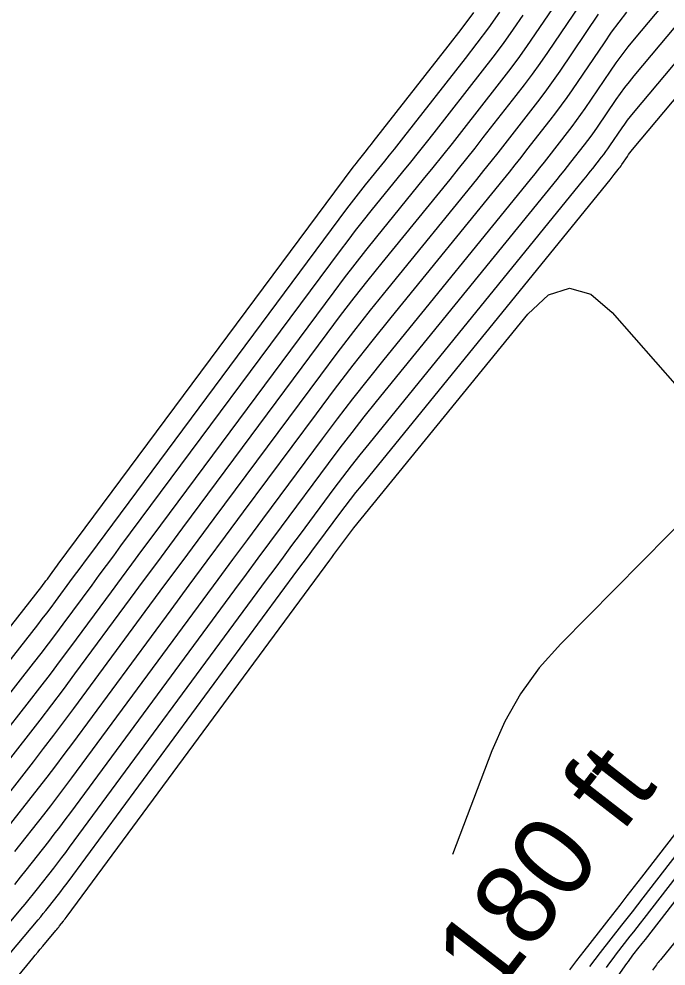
# Model space of a CAD drawing. Extents: x 7585033 to 7595090, y 547091 to 553471.
# Drawn here: x 7587152.7 to 7587203.3, y 548340.9 to 548414.8 of the extents above; entities that cross this region are included whole.
import ezdxf

# ---------------------------------------------------------------- set-up
doc = ezdxf.new("R2010")
doc.units = 0
for name, color, linetype in [('E_TERR_DSPLAY_GeneralTx', 7, 'Continuous'), ('E_TERR_DSPLAY_MajContour', 7, 'Continuous'), ('E_TERR_DSPLAY_MinContour', 7, 'Continuous')]:
    doc.layers.add(name, color=color, linetype=linetype)

msp = doc.modelspace()

# ---------------------------------------------------------------- linework, layer by layer
at = {"layer": 'E_TERR_DSPLAY_MajContour'}
for points in [[(7587216.392, 548431.831), (7587200.8, 548413.242), (7587200.305, 548412.638), (7587199.827, 548412.021), (7587199.365, 548411.392), (7587198.918, 548410.751), (7587196.942, 548407.837), (7587196.61, 548407.357), (7587196.27, 548406.882), (7587195.921, 548406.413), (7587195.565, 548405.95), (7587194.124, 548404.111), (7587193.762, 548403.652), (7587193.399, 548403.194), (7587193.033, 548402.738), (7587192.666, 548402.284), (7587181.228, 548388.221), (7587180.001, 548386.696), (7587178.791, 548385.157), (7587177.598, 548383.606), (7587176.422, 548382.041), (7587171.751, 548375.755), (7587170.584, 548374.183), (7587169.418, 548372.61), (7587168.254, 548371.036), (7587167.091, 548369.461), (7587156.836, 548355.558), (7587156.294, 548354.828), (7587155.746, 548354.102), (7587155.192, 548353.381), (7587154.633, 548352.663), (7587152.387, 548349.802)], [(7587197.116, 548419.631), (7587193.072, 548413.667), (7587192.392, 548412.683), (7587191.696, 548411.712), (7587190.983, 548410.753), (7587190.254, 548409.805), (7587187.304, 548406.041), (7587186.564, 548405.101), (7587185.821, 548404.165), (7587185.072, 548403.232), (7587184.32, 548402.303), (7587180.665, 548397.809), (7587179.811, 548396.747), (7587178.968, 548395.675), (7587178.136, 548394.594), (7587177.317, 548393.503), (7587163.108, 548374.38), (7587162.311, 548373.308), (7587161.516, 548372.235), (7587160.722, 548371.161), (7587159.928, 548370.086), (7587156.756, 548365.786), (7587155.959, 548364.714), (7587155.154, 548363.648), (7587154.342, 548362.588), (7587153.521, 548361.534), (7587148.87, 548355.611)], [(7587130.311, 548312.87), (7587153.801, 548341.463), (7587153.995, 548341.698), (7587154.19, 548341.933), (7587154.385, 548342.168), (7587154.581, 548342.402), (7587155.605, 548343.624), (7587155.68, 548343.716), (7587155.755, 548343.807), (7587155.83, 548343.9), (7587155.903, 548343.993), (7587156.196, 548344.366), (7587156.269, 548344.459), (7587156.341, 548344.553), (7587156.413, 548344.648), (7587156.483, 548344.743), (7587177.005, 548372.565), (7587177.161, 548372.777), (7587177.317, 548372.988), (7587177.474, 548373.199), (7587177.63, 548373.41), (7587178.257, 548374.253), (7587178.414, 548374.462), (7587178.574, 548374.671), (7587178.737, 548374.877), (7587178.901, 548375.081), (7587192.474, 548391.769), (7587194.099, 548393.268), (7587195.743, 548393.788), (7587197.406, 548393.33), (7587199.086, 548391.894), (7587205.846, 548384.193)], [(7587205.62, 548376.702), (7587195.055, 548366.03), (7587193.376, 548364.151), (7587191.919, 548362.129), (7587190.685, 548359.964), (7587189.673, 548357.656), (7587186.609, 548349.565)], [(7587198.63, 548340.753), (7587198.888, 548341.106), (7587199.151, 548341.455), (7587199.418, 548341.801), (7587200.494, 548343.179), (7587200.763, 548343.524), (7587201.032, 548343.869), (7587201.3, 548344.214), (7587201.568, 548344.559), (7587222.895, 548372.105)]]:
    msp.add_lwpolyline(points, dxfattribs=at)
at = {"layer": 'E_TERR_DSPLAY_MinContour'}
for points in [[(7587151.496, 548341.202), (7587154.227, 548344.462), (7587154.429, 548344.706), (7587154.63, 548344.951), (7587154.828, 548345.197), (7587155.024, 548345.445), (7587155.805, 548346.44), (7587156, 548346.69), (7587156.192, 548346.94), (7587156.383, 548347.193), (7587156.571, 548347.447), (7587174.527, 548371.789), (7587174.935, 548372.342), (7587175.343, 548372.893), (7587175.751, 548373.445), (7587176.16, 548373.996), (7587177.798, 548376.2), (7587178.21, 548376.748), (7587178.628, 548377.292), (7587179.053, 548377.832), (7587179.483, 548378.366), (7587198.925, 548402.271), (7587199.004, 548402.368), (7587199.082, 548402.466), (7587199.161, 548402.565), (7587199.238, 548402.663), (7587199.548, 548403.059), (7587199.625, 548403.158), (7587199.7, 548403.259), (7587199.773, 548403.361), (7587199.844, 548403.465), (7587200.269, 548404.091), (7587200.365, 548404.229), (7587200.465, 548404.364), (7587200.568, 548404.497), (7587200.674, 548404.627), (7587224.859, 548433.46)], [(7587222.037, 548432.917), (7587200.716, 548407.499), (7587200.48, 548407.211), (7587200.252, 548406.917), (7587200.032, 548406.617), (7587199.819, 548406.311), (7587198.877, 548404.922), (7587198.719, 548404.693), (7587198.556, 548404.467), (7587198.39, 548404.243), (7587198.221, 548404.023), (7587197.533, 548403.146), (7587197.361, 548402.927), (7587197.188, 548402.709), (7587197.014, 548402.492), (7587196.838, 548402.275), (7587180.064, 548381.651), (7587179.369, 548380.786), (7587178.683, 548379.914), (7587178.006, 548379.034), (7587177.339, 548378.147), (7587174.691, 548374.582), (7587174.029, 548373.691), (7587173.368, 548372.799), (7587172.708, 548371.906), (7587172.048, 548371.013), (7587156.66, 548350.15), (7587156.353, 548349.738), (7587156.043, 548349.328), (7587155.731, 548348.92), (7587155.415, 548348.514), (7587154.145, 548346.897), (7587153.826, 548346.494), (7587153.504, 548346.094), (7587153.178, 548345.696), (7587152.85, 548345.301), (7587148.411, 548340.002)], [(7587219.214, 548432.374), (7587200.758, 548410.371), (7587200.393, 548409.924), (7587200.04, 548409.469), (7587199.698, 548409.004), (7587199.368, 548408.531), (7587197.909, 548406.38), (7587197.664, 548406.025), (7587197.413, 548405.674), (7587197.156, 548405.328), (7587196.893, 548404.986), (7587195.829, 548403.628), (7587195.562, 548403.289), (7587195.293, 548402.952), (7587195.023, 548402.615), (7587194.752, 548402.28), (7587180.646, 548384.936), (7587179.685, 548383.741), (7587178.737, 548382.536), (7587177.802, 548381.32), (7587176.88, 548380.094), (7587173.221, 548375.169), (7587172.306, 548373.937), (7587171.393, 548372.704), (7587170.481, 548371.471), (7587169.57, 548370.237), (7587156.748, 548352.854), (7587156.323, 548352.283), (7587155.894, 548351.715), (7587155.461, 548351.15), (7587155.024, 548350.589), (7587153.266, 548348.349), (7587152.824, 548347.791), (7587152.378, 548347.237)], [(7587149.749, 548354.159), (7587153.461, 548358.886), (7587154.385, 548360.072), (7587155.299, 548361.264), (7587156.204, 548362.463), (7587157.101, 548363.669), (7587161.446, 548369.56), (7587162.469, 548370.945), (7587163.492, 548372.328), (7587164.517, 548373.711), (7587165.542, 548375.093), (7587176.812, 548390.259), (7587177.862, 548391.656), (7587178.928, 548393.042), (7587180.008, 548394.416), (7587181.104, 548395.778), (7587186.406, 548402.298), (7587187.063, 548403.109), (7587187.715, 548403.922), (7587188.364, 548404.739), (7587189.009, 548405.558), (7587191.582, 548408.842), (7587192.218, 548409.668), (7587192.84, 548410.504), (7587193.447, 548411.352), (7587194.039, 548412.21), (7587197.566, 548417.411)], [(7587146.233, 548359.968), (7587154.508, 548370.508), (7587154.619, 548370.65), (7587154.729, 548370.794), (7587154.838, 548370.938), (7587154.945, 548371.082), (7587155.374, 548371.663), (7587155.481, 548371.809), (7587155.588, 548371.954), (7587155.696, 548372.099), (7587155.803, 548372.244), (7587178.833, 548403.237), (7587178.96, 548403.405), (7587179.088, 548403.572), (7587179.218, 548403.738), (7587179.35, 548403.902), (7587179.883, 548404.556), (7587180.015, 548404.72), (7587180.147, 548404.885), (7587180.278, 548405.05), (7587180.409, 548405.215), (7587186.271, 548412.697), (7587187.28, 548414.007), (7587188.266, 548415.334)], [(7587190.283, 548415.347), (7587189.409, 548414.127), (7587188.515, 548412.922), (7587187.599, 548411.733), (7587182.776, 548405.579), (7587182.408, 548405.111), (7587182.038, 548404.645), (7587181.665, 548404.181), (7587181.291, 548403.718), (7587179.789, 548401.871), (7587179.416, 548401.408), (7587179.048, 548400.94), (7587178.685, 548400.468), (7587178.328, 548399.992), (7587158.238, 548372.956), (7587157.901, 548372.502), (7587157.564, 548372.047), (7587157.228, 548371.593), (7587156.892, 548371.138), (7587155.549, 548369.317), (7587155.212, 548368.863), (7587154.871, 548368.412), (7587154.526, 548367.963), (7587154.179, 548367.517), (7587147.112, 548358.515)], [(7587192.104, 548415.124), (7587191.338, 548414.015), (7587190.553, 548412.919), (7587189.749, 548411.837), (7587188.927, 548410.769), (7587185.144, 548405.942), (7587184.538, 548405.172), (7587183.929, 548404.405), (7587183.316, 548403.641), (7587182.699, 548402.88), (7587180.227, 548399.84), (7587179.613, 548399.077), (7587179.008, 548398.307), (7587178.411, 548397.531), (7587177.822, 548396.748), (7587160.673, 548373.668), (7587160.106, 548372.905), (7587159.54, 548372.141), (7587158.975, 548371.377), (7587158.41, 548370.612), (7587156.153, 548367.551), (7587155.585, 548366.788), (7587155.013, 548366.03), (7587154.434, 548365.275), (7587153.85, 548364.525), (7587147.991, 548357.063)], [(7587150.628, 548352.706), (7587153.852, 548356.812), (7587154.654, 548357.841), (7587155.448, 548358.877), (7587156.234, 548359.918), (7587157.013, 548360.965), (7587162.965, 548369.034), (7587164.215, 548370.729), (7587165.468, 548372.422), (7587166.722, 548374.114), (7587167.977, 548375.805), (7587176.307, 548387.015), (7587177.588, 548388.719), (7587178.887, 548390.41), (7587180.205, 548392.086), (7587181.542, 548393.747), (7587188.493, 548402.294), (7587189.053, 548402.985), (7587189.61, 548403.68), (7587190.163, 548404.376), (7587190.714, 548405.076), (7587192.91, 548407.878), (7587193.452, 548408.583), (7587193.983, 548409.297), (7587194.501, 548410.02), (7587195.007, 548410.752), (7587198.017, 548415.191)], [(7587151.508, 548351.254), (7587154.243, 548354.738), (7587154.923, 548355.611), (7587155.597, 548356.489), (7587156.264, 548357.373), (7587156.924, 548358.261), (7587164.613, 548368.685), (7587166.027, 548370.601), (7587167.444, 548372.516), (7587168.862, 548374.429), (7587170.281, 548376.341), (7587175.963, 548383.988), (7587177.394, 548385.891), (7587178.845, 548387.779), (7587180.317, 548389.651), (7587181.809, 548391.506), (7587190.579, 548402.289), (7587191.043, 548402.862), (7587191.504, 548403.437), (7587191.963, 548404.014), (7587192.419, 548404.593), (7587194.237, 548406.914), (7587194.687, 548407.498), (7587195.126, 548408.089), (7587195.555, 548408.688), (7587195.974, 548409.295), (7587198.467, 548412.971), (7587199.031, 548413.78), (7587199.614, 548414.573), (7587200.218, 548415.351)], [(7587177.99, 548309.416), (7587200.23, 548341.062), (7587200.345, 548341.223), (7587200.462, 548341.382), (7587200.58, 548341.54), (7587200.701, 548341.697), (7587201.188, 548342.32), (7587201.31, 548342.476), (7587201.431, 548342.632), (7587201.553, 548342.788), (7587201.674, 548342.944), (7587225.529, 548373.755)], [(7587228.144, 548372.494), (7587202.84, 548341.344), (7587202.761, 548341.245), (7587202.682, 548341.146), (7587202.605, 548341.046), (7587202.528, 548340.945), (7587202.223, 548340.539)], [(7587220.261, 548370.455), (7587201.462, 548346.174), (7587201.047, 548345.64), (7587200.632, 548345.105), (7587200.217, 548344.572), (7587199.8, 548344.038), (7587198.134, 548341.906), (7587197.721, 548341.37), (7587197.315, 548340.829)], [(7587217.627, 548368.805), (7587201.356, 548347.789), (7587200.795, 548347.066), (7587200.233, 548346.342), (7587199.67, 548345.62), (7587199.106, 548344.897), (7587196.85, 548342.01), (7587196.291, 548341.285), (7587195.741, 548340.553)]]:
    msp.add_lwpolyline(points, dxfattribs=at)

# ---------------------------------------------------------------- texts
at = {"layer": 'E_TERR_DSPLAY_GeneralTx'}
msp.add_text('180 ft', height=6.3, rotation=52.26842, dxfattribs=at).set_placement((7587189.771, 548338.209))

doc.saveas('drawing.dxf')
